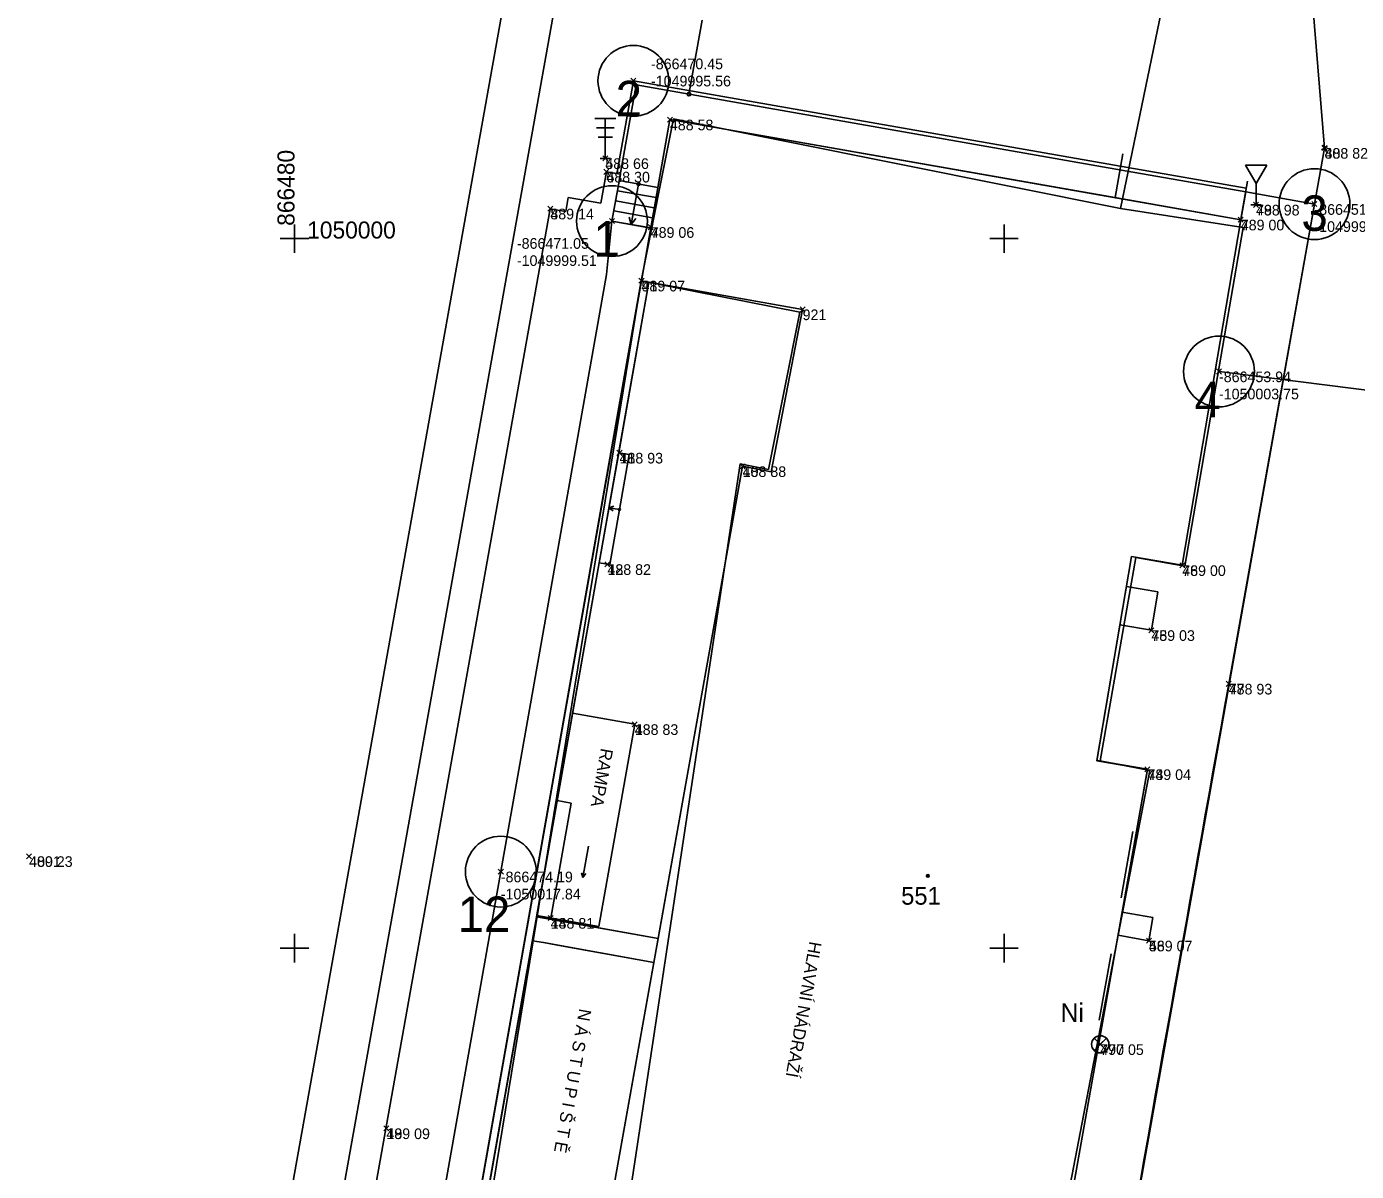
# Model space of a CAD drawing. Extents: x -866624 to -866276, y -1050208 to -1049940.
# Drawn here: x -866487.55 to -866450.07, y -1050026.29 to -1049994.03 of the extents above; entities that cross this region are included whole.
import ezdxf

# ---------------------------------------------------------------- set-up
doc = ezdxf.new("R2010")
doc.units = 0
for name, color, linetype in [('00_BODY VYTYČ', 7, 'Continuous'), ('00_POMOCNÉ KCE', 7, 'Continuous'), ('09_PODLAHY', 7, 'Continuous'), ('bod-cislo', 7, 'Continuous'), ('bod-oznac', 7, 'Continuous'), ('bod-vyska', 7, 'Continuous'), ('BUDOVY', 7, 'Continuous'), ('CTV-SIT', 7, 'Continuous'), ('Default', 7, 'Continuous'), ('DOPR-ZAR', 7, 'Continuous'), ('HRAN-LIN', 7, 'Continuous'), ('Hranice', 7, 'Continuous'), ('Hranice další', 7, 'Continuous'), ('Hranice-budov', 7, 'Continuous'), ('KOLEJ', 7, 'Continuous'), ('Parcela-stavebni', 7, 'Continuous'), ('SIT_05_NÁVRH PLYN', 7, 'Continuous'), ('TEXT', 7, 'Continuous'), ('VCHOD', 7, 'Continuous'), ('ZABRADLI', 7, 'Continuous'), ('znacky-budov', 7, 'Continuous')]:
    doc.layers.add(name, color=color, linetype=linetype)

# ---------------------------------------------------------------- blocks, each defined once
blk = doc.blocks.new('s_zdena')
at = {"layer": 'Default'}
blk.add_circle((0, 0), 0.175, dxfattribs=at)
for start, end in [(0, 180), (180, 0)]:
    blk.add_arc((0, 0), 0.0875, start, end, dxfattribs=at)
blk = doc.blocks.new('POINT_DISPLAY')
at = {"layer": 'Default'}
for p, q in [((-0.071, 0.071), (0.071, -0.071)), ((0.071, 0.071), (-0.071, -0.071))]:
    blk.add_line(p, q, dxfattribs=at)
blk = doc.blocks.new('A$C7737496A')
at = {"layer": 'DOPR-ZAR'}
for p, q in [((0, 1.119), (0.6, 1.119)), ((0.049, 0.859), (0.551, 0.859)), ((0.3, 1.119), (0.3, 0)), ((0.098, 0.599), (0.502, 0.599)), ((0.449, 0), (0.151, 0))]:
    blk.add_line(p, q, dxfattribs=at)
blk = doc.blocks.new('200DZ')
at = {"layer": 'DOPR-ZAR'}
for p, q in [((-0.149, 0), (0.149, 0)), ((0, -0.599), (0, 0)), ((-0.3, -1.119), (0, -0.599)), ((0, -0.599), (0.3, -1.119)), ((0, -1.119), (-0.3, -1.119)), ((0.3, -1.119), (0, -1.119))]:
    blk.add_line(p, q, dxfattribs=at)
blk = doc.blocks.new('CTVSIT')
at = {"layer": 'Default'}
for p, q in [((0, 2), (0, -2)), ((-2, 0), (2, 0))]:
    blk.add_line(p, q, dxfattribs=at)
blk = doc.blocks.new('vytyčení')
at = {"layer": '00_POMOCNÉ KCE'}
blk.add_lwpolyline([(-866088.569, -1050068.4), (-866082.964, -1050067.078), (-866067.63, -1050067.491)], dxfattribs=at)
for centre in [(-866081.359, -1050067.121), (-866076.292, -1050069.077), (-866081.926, -1050086.621), (-866077.927, -1050086.627), (-866059.331, -1050086.985)]:
    blk.add_circle(centre, 0.998, dxfattribs=at)
blk.add_arc((-865794.817, -1039948.575), 10122.593, 268.4556412, 268.567516, dxfattribs=at)
at = {"layer": '09_PODLAHY'}
for points in [[(-866081.414, -1050069.09), (-866081.361, -1050067.121), (-866034.112, -1050068.345), (-866032.646, -1050070.404), (-866032.668, -1050071.704), (-866032.671, -1050071.836), (-866032.872, -1050071.831), (-866032.905, -1050071.604), (-866037.17, -1050071.494), (-866046.156, -1050071.254), (-866052.647, -1050071.161), (-866052.609, -1050069.711), (-866064.905, -1050069.395), (-866064.942, -1050070.845), (-866070.764, -1050070.735), (-866070.738, -1050069.285), (-866080.614, -1050069.109), (-866081.414, -1050069.09)], [(-866079.269, -1050086.691), (-866081.926, -1050086.621), (-866081.593, -1050072.473), (-866081.514, -1050069.088)], [(-866080.464, -1050069.113), (-866081.713, -1050069.081)], [(-866080.998, -1050085.44), (-866080.693, -1050072.494), (-866080.614, -1050069.109)], [(-866080.706, -1050072.708), (-866081.955, -1050072.676)], [(-866037.659, -1050086.526), (-866042.227, -1050086.418), (-866042.221, -1050086.198), (-866057.536, -1050085.815), (-866068.352, -1050085.544), (-866071.502, -1050085.465), (-866076.384, -1050085.343), (-866076.386, -1050085.562), (-866042.227, -1050086.418)]]:
    blk.add_lwpolyline(points, dxfattribs=at)
for points in [[(-866080.998, -1050085.44), (-866079.056, -1050085.493), (-866079.086, -1050086.595), (-866081.824, -1050086.525), (-866081.493, -1050072.476), (-866081.414, -1050069.09), (-866080.614, -1050069.109)], [(-866058.222, -1050085.797), (-866058.13, -1050082.317), (-866071.644, -1050081.953), (-866071.61, -1050081.134), (-866076.267, -1050080.942), (-866076.384, -1050085.343), (-866058.222, -1050085.797)], [(-866058.219, -1050085.479), (-866058.206, -1050085.079), (-866058.13, -1050082.317), (-866057.447, -1050082.335), (-866057.523, -1050085.097), (-866057.533, -1050085.497), (-866057.536, -1050085.815), (-866058.222, -1050085.797), (-866058.219, -1050085.479)], [(-866042.22, -1050086.198), (-866042.104, -1050082.475), (-866046.696, -1050082.351), (-866046.704, -1050082.624), (-866057.447, -1050082.335), (-866057.533, -1050085.497), (-866057.536, -1050085.815), (-866042.22, -1050086.198)], [(-866076.389, -1050085.553), (-866077.898, -1050085.519), (-866077.927, -1050086.627), (-866076.412, -1050086.552), (-866042.25, -1050087.417), (-866029.271, -1050087.726), (-866029.245, -1050086.729)]]:
    blk.add_lwpolyline(points, close=True, dxfattribs=at)
at = {"layer": 'SIT_05_NÁVRH PLYN'}
blk.add_lwpolyline([(-866082.454, -1050060.072), (-866076.494, -1050060.691), (-866076.292, -1050069.077)], dxfattribs=at)
at = {"layer": '09_PODLAHY', "rotation": -98.59344504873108}
blk.add_blockref('POINT_DISPLAY', (-866082.964, -1050067.078), dxfattribs=at)

msp = doc.modelspace()

# ---------------------------------------------------------------- linework, layer by layer
at = {"layer": 'bod-vyska'}
for p, q in [((-866457.118, -1050022.882), (-866457.462, -1050022.538)), ((-866457.118, -1050022.538), (-866457.462, -1050022.882))]:
    msp.add_line(p, q, dxfattribs=at)
for points in [[(-866457.462, -1050022.882), (-866457.29, -1050022.71), (-866457.462, -1050022.538), (-866457.462, -1050022.538)], [(-866457.118, -1050022.538), (-866457.29, -1050022.71), (-866457.118, -1050022.882)]]:
    msp.add_lwpolyline(points, dxfattribs=at)
msp.add_circle((-866457.29, -1050022.71), 0.243, dxfattribs=at)
for start, end in [(135, 180), (180, 225), (0, 45), (315, 360)]:
    msp.add_arc((-866457.29, -1050022.71), 0.243, start, end, dxfattribs=at)
at = {"layer": 'BUDOVY'}
for p, q in [((-866469.42, -1049996.65), (-866470.22, -1050001.19)), ((-866469.42, -1049996.65), (-866453.33, -1049999.47)), ((-866453.33, -1049999.47), (-866454.98, -1050009.21)), ((-866470.22, -1050001.19), (-866465.68, -1050002)), ((-866465.68, -1050002), (-866466.565, -1050006.576)), ((-866471.76, -1050030.98), (-866467.37, -1050006.42)), ((-866466.565, -1050006.576), (-866467.37, -1050006.42)), ((-866456.409, -1050008.966), (-866457.389, -1050014.716)), ((-866456.409, -1050008.966), (-866454.98, -1050009.21)), ((-866455.96, -1050014.96), (-866458.11, -1050027.07)), ((-866455.96, -1050014.96), (-866457.389, -1050014.716))]:
    msp.add_line(p, q, dxfattribs=at)
at = {"layer": 'HRAN-LIN'}
for p, q in [((-866471.21, -1049998.12), (-866471.369, -1049999.008)), ((-866471.21, -1049998.12), (-866470.816, -1049998.19)), ((-866470.816, -1049998.19), (-866471.052, -1049999.51)), ((-866470.848, -1049998.368), (-866469.757, -1049998.563)), ((-866470.302, -1049998.465), (-866470.507, -1049999.607)), ((-866472.286, -1049998.844), (-866472.357, -1049999.238)), ((-866472.286, -1049998.844), (-866471.369, -1049999.008)), ((-866470.899, -1049998.653), (-866469.808, -1049998.848)), ((-866472.79, -1049999.16), (-866484.714, -1050065.787)), ((-866472.79, -1049999.16), (-866472.357, -1049999.238)), ((-866471.001, -1049999.224), (-866469.91, -1049999.419)), ((-866470.95, -1049998.939), (-866469.859, -1049999.134)), ((-866471.052, -1049999.51), (-866469.961, -1049999.705)), ((-866470.507, -1049999.607), (-866470.569, -1049999.398)), ((-866470.507, -1049999.607), (-866470.376, -1049999.433)), ((-866475.964, -1050034.88), (-866470.013, -1050001.227)), ((-866471.117, -1050009.191), (-866470.568, -1050006.088)), ((-866470.864, -1050006.036), (-866470.568, -1050006.088)), ((-866471.138, -1050007.587), (-866470.999, -1050007.546)), ((-866471.138, -1050007.587), (-866470.842, -1050007.64)), ((-866471.138, -1050007.587), (-866471.021, -1050007.674)), ((-866471.412, -1050009.139), (-866471.117, -1050009.191)), ((-866455.665, -1050009.956), (-866456.552, -1050009.804)), ((-866455.665, -1050009.956), (-866455.85, -1050011.04)), ((-866455.85, -1050011.04), (-866456.737, -1050010.889)), ((-866472.162, -1050013.38), (-866470.41, -1050013.69)), ((-866471.418, -1050019.391), (-866470.41, -1050013.69)), ((-866472.78, -1050019.15), (-866472.207, -1050015.911)), ((-866472.597, -1050015.842), (-866472.207, -1050015.911)), ((-866471.871, -1050018.012), (-866471.715, -1050017.126)), ((-866471.871, -1050018.012), (-866471.913, -1050017.873)), ((-866471.871, -1050018.012), (-866471.785, -1050017.896)), ((-866473.17, -1050019.081), (-866471.418, -1050019.391)), ((-866455.805, -1050019.14), (-866456.675, -1050018.986)), ((-866455.92, -1050019.79), (-866455.805, -1050019.14)), ((-866455.92, -1050019.79), (-866456.79, -1050019.636))]:
    msp.add_line(p, q, dxfattribs=at)
msp.add_lwpolyline([(-866451.44, -1049991.71), (-866450.97, -1049997.45), (-866453.67, -1050012.55)], dxfattribs=at)
for centre, radius in [((-866470.302, -1049998.465), 0.0424), ((-866470.842, -1050007.64), 0.0283)]:
    msp.add_circle(centre, radius, dxfattribs=at)
msp.add_arc((-856489.119, -1051794.291), 10122.592, 169.8621961, 169.9740709, dxfattribs=at)
at = {"layer": 'Hranice'}
for p, q in [((-866455.52, -1049993.35), (-866456.72, -1049999.15)), ((-866469.32, -1049996.63), (-866470.23, -1050001.19)), ((-866469.32, -1049996.63), (-866456.72, -1049999.15)), ((-866456.72, -1049999.15), (-866453.26, -1049999.69)), ((-866454.91, -1050009.23), (-866453.26, -1049999.69)), ((-866475.7, -1050034.65), (-866470.23, -1050001.19)), ((-866456.29, -1050008.99), (-866457.29, -1050014.72)), ((-866454.91, -1050009.23), (-866456.29, -1050008.99)), ((-866455.89, -1050014.99), (-866458.22, -1050027.11)), ((-866457.29, -1050014.72), (-866455.89, -1050014.99))]:
    msp.add_line(p, q, dxfattribs=at)
at = {"layer": 'Hranice další'}
for p, q in [((-866470.23, -1050001.19), (-866465.76, -1050002.08)), ((-866465.76, -1050002.08), (-866466.64, -1050006.51)), ((-866467.44, -1050006.35), (-866471.83, -1050035.4)), ((-866466.64, -1050006.51), (-866467.44, -1050006.35))]:
    msp.add_line(p, q, dxfattribs=at)
at = {"layer": 'Hranice-budov'}
for p, q in [((-866469.32, -1049996.63), (-866470.23, -1050001.19)), ((-866469.32, -1049996.63), (-866456.72, -1049999.15)), ((-866456.72, -1049999.15), (-866453.26, -1049999.69)), ((-866454.91, -1050009.23), (-866453.26, -1049999.69)), ((-866470.23, -1050001.19), (-866465.76, -1050002.08)), ((-866465.76, -1050002.08), (-866466.64, -1050006.51)), ((-866467.44, -1050006.35), (-866471.83, -1050035.4)), ((-866466.64, -1050006.51), (-866467.44, -1050006.35)), ((-866456.29, -1050008.99), (-866457.29, -1050014.72)), ((-866454.91, -1050009.23), (-866456.29, -1050008.99)), ((-866455.89, -1050014.99), (-866458.22, -1050027.11)), ((-866457.29, -1050014.72), (-866455.89, -1050014.99))]:
    msp.add_line(p, q, dxfattribs=at)
at = {"layer": 'KOLEJ'}
for p, q in [((-866473.069, -1049987.559), (-866486.976, -1050065.382)), ((-866471.656, -1049987.812), (-866485.563, -1050065.635))]:
    msp.add_line(p, q, dxfattribs=at)
at = {"layer": 'VCHOD'}
for p, q in [((-866456.705, -1050018.584), (-866456.373, -1050016.713)), ((-866457.317, -1050022.033), (-866456.985, -1050020.162))]:
    msp.add_line(p, q, dxfattribs=at)
at = {"layer": 'ZABRADLI'}
msp.add_line((-866468.51, -1049993.85), (-866468.874, -1049995.883), dxfattribs=at)
msp.add_circle((-866468.883, -1049995.932), 0.05, dxfattribs=at)

# ---------------------------------------------------------------- block references
at = {"layer": '00_BODY VYTYČ'}
for p in [(-866470.449, -1049995.556), (-866451.253, -1049999.031), (-866471.052, -1049999.51), (-866453.944, -1050003.748), (-866474.185, -1050017.843)]:
    msp.add_blockref('POINT_DISPLAY', p, dxfattribs=at)
at = {"layer": '00_POMOCNÉ KCE', "rotation": -98.59344504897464}
msp.add_blockref('vytyčení', (42415.469, -2063260.675), dxfattribs=at)
at = {"layer": '00_POMOCNÉ KCE'}
for p in [(-866470.449, -1049995.556), (-866451.253, -1049999.031), (-866471.052, -1049999.51), (-866453.944, -1050003.748), (-866474.185, -1050017.843)]:
    msp.add_blockref('POINT_DISPLAY', p, dxfattribs=at)
at = {"layer": 'bod-oznac'}
for p in [(-866469.42, -1049996.65), (-866450.97, -1049997.45), (-866471.24, -1049997.74), (-866471.21, -1049998.12), (-866472.79, -1049999.16), (-866452.9, -1049999.05), (-866469.96, -1049999.68), (-866453.33, -1049999.47), (-866470.22, -1050001.19), (-866465.68, -1050002), (-866470.84, -1050006.04), (-866467.37, -1050006.42), (-866471.18, -1050009.18), (-866454.98, -1050009.21), (-866455.85, -1050011.04), (-866453.67, -1050012.55), (-866470.41, -1050013.69), (-866455.96, -1050014.96), (-866487.48, -1050017.41), (-866472.78, -1050019.15), (-866455.92, -1050019.79), (-866457.29, -1050022.71), (-866477.41, -1050025.08)]:
    msp.add_blockref('POINT_DISPLAY', p, dxfattribs=at)
at = {"layer": 'CTV-SIT', "xscale": 0.19999999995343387, "yscale": 0.19999999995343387}
for p in [(-866480, -1050000), (-866460, -1050000), (-866480, -1050020), (-866460, -1050020)]:
    msp.add_blockref('CTVSIT', p, dxfattribs=at)
at = {"layer": 'DOPR-ZAR'}
msp.add_blockref('A$C7737496A', (-866471.54, -1049997.74), dxfattribs=at)
at = {"layer": 'DOPR-ZAR', "rotation": 179.99999999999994}
msp.add_blockref('200DZ', (-866452.9, -1049999.05), dxfattribs=at)
at = {"layer": 'znacky-budov', "xscale": 0.2, "yscale": 0.20000000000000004}
msp.add_blockref('s_zdena', (-866462.15, -1050017.96), dxfattribs=at)

# ---------------------------------------------------------------- texts
at = {"layer": '00_BODY VYTYČ'}
for s, p in [('2', (-866470.949, -1049996.556)), ('3', (-866451.621, -1049999.785)), ('1', (-866471.572, -1050000.51)), ('4', (-866454.635, -1050005.035)), ('12', (-866475.403, -1050019.544))]:
    msp.add_text(s, height=1, dxfattribs=at).set_placement(p)
at = {"layer": '00_POMOCNÉ KCE'}
for s, p in [('-866470.45', (-866469.952, -1049995.229)), ('-1049995.56', (-866469.952, -1049995.713)), ('-866451.25', (-866451.253, -1049999.331)), ('-1049999.03', (-866451.253, -1049999.814)), ('-866471.05', (-866473.732, -1050000.289)), ('-1049999.51', (-866473.732, -1050000.773)), ('-866453.94', (-866453.944, -1050004.048)), ('-1050003.75', (-866453.944, -1050004.532)), ('-866474.19', (-866474.185, -1050018.143)), ('-1050017.84', (-866474.185, -1050018.626))]:
    msp.add_text(s, height=0.3, dxfattribs=at).set_placement(p)
at = {"layer": 'bod-cislo'}
for s, p in [('4', (-866469.42, -1049996.95)), ('5', (-866471.24, -1049998.04)), ('80', (-866450.97, -1049997.75)), ('6', (-866471.21, -1049998.42)), ('8', (-866472.79, -1049999.46)), ('79', (-866452.9, -1049999.35)), ('78', (-866453.33, -1049999.77)), ('7', (-866469.96, -1049999.98)), ('91', (-866470.22, -1050001.49)), ('921', (-866465.68, -1050002.3)), ('11', (-866470.84, -1050006.34)), ('10', (-866467.37, -1050006.72)), ('12', (-866471.18, -1050009.48)), ('76', (-866454.98, -1050009.51)), ('75', (-866455.85, -1050011.34)), ('77', (-866453.67, -1050012.85)), ('13', (-866470.41, -1050013.99)), ('74', (-866455.96, -1050015.26)), ('4001', (-866487.48, -1050017.71)), ('14', (-866472.78, -1050019.45)), ('56', (-866455.92, -1050020.09)), ('777', (-866457.29, -1050023.01)), ('19', (-866477.41, -1050025.38))]:
    msp.add_text(s, height=0.3, dxfattribs=at).set_placement(p)
at = {"layer": 'bod-vyska'}
for s, p in [('488 58', (-866469.42, -1049996.95)), ('488 66', (-866471.24, -1049998.04)), ('488 82', (-866450.97, -1049997.75)), ('488 30', (-866471.21, -1049998.42)), ('489 14', (-866472.79, -1049999.46)), ('488 98', (-866452.9, -1049999.35)), ('489 00', (-866453.33, -1049999.77)), ('489 06', (-866469.96, -1049999.98)), ('489 07', (-866470.22, -1050001.49)), ('488 93', (-866470.84, -1050006.34)), ('488 88', (-866467.37, -1050006.72)), ('488 82', (-866471.18, -1050009.48)), ('489 00', (-866454.98, -1050009.51)), ('489 03', (-866455.85, -1050011.34)), ('488 93', (-866453.67, -1050012.85)), ('488 83', (-866470.41, -1050013.99)), ('489 04', (-866455.96, -1050015.26)), ('489 23', (-866487.48, -1050017.71)), ('488 81', (-866472.78, -1050019.45)), ('489 07', (-866455.92, -1050020.09)), ('490 05', (-866457.29, -1050023.01)), ('489 09', (-866477.41, -1050025.38))]:
    msp.add_text(s, height=0.3, dxfattribs=at).set_placement(p)
at = {"layer": 'CTV-SIT'}
msp.add_text('  866480', height=0.48, rotation=90, dxfattribs=at).set_placement((-866480, -1050000))
msp.add_text('  1050000', height=0.48, dxfattribs=at).set_placement((-866480, -1050000))
at = {"layer": 'Parcela-stavebni'}
msp.add_text('551', height=0.5, dxfattribs=at).set_placement((-866462.902, -1050018.774))
at = {"layer": 'TEXT'}
for s, p in [('RAMPA', (-866471.363, -1050014.349)), ('HLAVNÍ NÁDRAŽÍ', (-866465.485, -1050019.793)), ('N Á S T U P I Š T Ě', (-866471.973, -1050021.688))]:
    msp.add_text(s, height=0.35, rotation=259.9728, dxfattribs=at).set_placement(p)
msp.add_text('Ni', height=0.525, dxfattribs=at).set_placement((-866458.411, -1050022.077))

doc.saveas('drawing.dxf')
